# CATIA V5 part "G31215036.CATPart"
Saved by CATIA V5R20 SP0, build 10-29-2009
Part number: G31215036
Revision: 8
Definition: design
Nomenclature: G31215036
Source: made
Description: NOT SPECIFIED
Bounding box of the stored display mesh (mm): x -6 to 36, y -12.31 to 12.31, z -12.5 to 12.5
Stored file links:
  C:\Users\Raffaele\Desktop\3D X SITO CF\BOLEX\23-BUSH REF 312\G31215036.CATPart

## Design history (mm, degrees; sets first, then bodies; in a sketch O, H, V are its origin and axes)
Body1 "MANIFOLD_SOLID_BREP #10163" (main body)
  Solid1: solid without history
Body2 "MANIFOLD_SOLID_BREP #10306"
  Solid2: solid without history
Body3 "MANIFOLD_SOLID_BREP #10449"
  Solid3: solid without history
Body4 "MANIFOLD_SOLID_BREP #10592"
  Solid4: solid without history
Body5 "MANIFOLD_SOLID_BREP #10735"
  Solid5: solid without history
Body6 "MANIFOLD_SOLID_BREP #10880"
  Solid6: solid without history
Body7 "MANIFOLD_SOLID_BREP #11025"
  Solid7: solid without history
Body8 "MANIFOLD_SOLID_BREP #11170"
  Solid8: solid without history
Body9 "MANIFOLD_SOLID_BREP #11315"
  Solid9: solid without history
Body10 "MANIFOLD_SOLID_BREP #11460"
  Solid10: solid without history
Body11 "MANIFOLD_SOLID_BREP #11605"
  Solid11: solid without history
Body12 "MANIFOLD_SOLID_BREP #11750"
  Solid12: solid without history
Body13 "MANIFOLD_SOLID_BREP #11895"
  Solid13: solid without history
Body14 "MANIFOLD_SOLID_BREP #12040"
  Solid14: solid without history
Body15 "MANIFOLD_SOLID_BREP #12185"
  Solid15: solid without history
Body16 "MANIFOLD_SOLID_BREP #12330"
  Solid16: solid without history
Body17 "MANIFOLD_SOLID_BREP #12475"
  Solid17: solid without history
Body18 "MANIFOLD_SOLID_BREP #12620"
  Solid18: solid without history
Body19 "MANIFOLD_SOLID_BREP #12765"
  Solid19: solid without history
Body20 "MANIFOLD_SOLID_BREP #12909"
  Solid20: solid without history
Body21 "MANIFOLD_SOLID_BREP #13052"
  Solid21: solid without history
Body22 "MANIFOLD_SOLID_BREP #13197"
  Solid22: solid without history
Body23 "MANIFOLD_SOLID_BREP #13341"
  Solid23: solid without history
Body24 "MANIFOLD_SOLID_BREP #13484"
  Solid24: solid without history
Body25 "MANIFOLD_SOLID_BREP #13629"
  Solid25: solid without history
Body26 "MANIFOLD_SOLID_BREP #13774"
  Solid26: solid without history
Body27 "MANIFOLD_SOLID_BREP #13919"
  Solid27: solid without history
Body28 "MANIFOLD_SOLID_BREP #14064"
  Solid28: solid without history
Body29 "MANIFOLD_SOLID_BREP #14209"
  Solid29: solid without history
Body30 "MANIFOLD_SOLID_BREP #14354"
  Solid30: solid without history
Body31 "MANIFOLD_SOLID_BREP #14499"
  Solid31: solid without history
Body32 "MANIFOLD_SOLID_BREP #14642"
  Solid32: solid without history
Body33 "MANIFOLD_SOLID_BREP #14785"
  Solid33: solid without history
Body34 "MANIFOLD_SOLID_BREP #14930"
  Solid34: solid without history
Body35 "MANIFOLD_SOLID_BREP #15075"
  Solid35: solid without history
Body36 "MANIFOLD_SOLID_BREP #15219"
  Solid36: solid without history
Body37 "MANIFOLD_SOLID_BREP #15362"
  Solid37: solid without history
Body38 "MANIFOLD_SOLID_BREP #15507"
  Solid38: solid without history
Body39 "MANIFOLD_SOLID_BREP #15651"
  Solid39: solid without history
Body40 "MANIFOLD_SOLID_BREP #15794"
  Solid40: solid without history
Body41 "MANIFOLD_SOLID_BREP #15939"
  Solid41: solid without history
Body42 "MANIFOLD_SOLID_BREP #16084"
  Solid42: solid without history
Body43 "MANIFOLD_SOLID_BREP #16229"
  Solid43: solid without history
Body44 "MANIFOLD_SOLID_BREP #16374"
  Solid44: solid without history
Body45 "MANIFOLD_SOLID_BREP #16519"
  Solid45: solid without history
Body46 "MANIFOLD_SOLID_BREP #16664"
  Solid46: solid without history
Body47 "MANIFOLD_SOLID_BREP #16809"
  Solid47: solid without history
Body48 "MANIFOLD_SOLID_BREP #16954"
  Solid48: solid without history
Body49 "MANIFOLD_SOLID_BREP #17099"
  Solid49: solid without history
Body50 "MANIFOLD_SOLID_BREP #17243"
  Solid50: solid without history
Body51 "MANIFOLD_SOLID_BREP #17386"
  Solid51: solid without history
Body52 "MANIFOLD_SOLID_BREP #17531"
  Solid52: solid without history
Body53 "MANIFOLD_SOLID_BREP #17675"
  Solid53: solid without history
Body54 "MANIFOLD_SOLID_BREP #17818"
  Solid54: solid without history
Body55 "MANIFOLD_SOLID_BREP #17963"
  Solid55: solid without history
Body56 "MANIFOLD_SOLID_BREP #18106"
  Solid56: solid without history
Body57 "MANIFOLD_SOLID_BREP #18249"
  Solid57: solid without history
Body58 "MANIFOLD_SOLID_BREP #18394"
  Solid58: solid without history
Body59 "MANIFOLD_SOLID_BREP #18539"
  Solid59: solid without history
Body60 "MANIFOLD_SOLID_BREP #18684"
  Solid60: solid without history
Body61 "MANIFOLD_SOLID_BREP #18829"
  Solid61: solid without history
Body62 "MANIFOLD_SOLID_BREP #18974"
  Solid62: solid without history
Body63 "MANIFOLD_SOLID_BREP #19119"
  Solid63: solid without history
Body64 "MANIFOLD_SOLID_BREP #19262"
  Solid64: solid without history
Body65 "MANIFOLD_SOLID_BREP #19405"
  Solid65: solid without history
Body66 "MANIFOLD_SOLID_BREP #19550"
  Solid66: solid without history
Body67 "MANIFOLD_SOLID_BREP #19695"
  Solid67: solid without history
Body68 "MANIFOLD_SOLID_BREP #19839"
  Solid68: solid without history
Body69 "MANIFOLD_SOLID_BREP #19982"
  Solid69: solid without history
Body70 "MANIFOLD_SOLID_BREP #20127"
  Solid70: solid without history
Body71 "MANIFOLD_SOLID_BREP #20271"
  Solid71: solid without history
Body72 "MANIFOLD_SOLID_BREP #20414"
  Solid72: solid without history
Body73 "MANIFOLD_SOLID_BREP #20559"
  Solid73: solid without history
